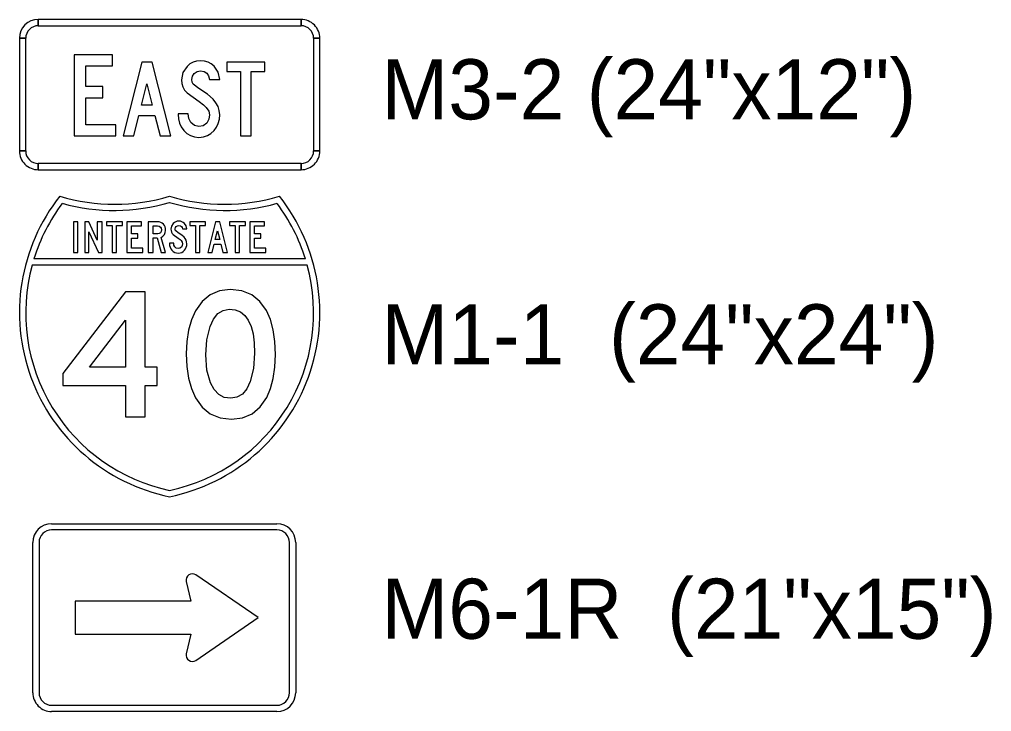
# Model space of a CAD drawing. Extents: x 620864 to 620948.6, y 415499.7 to 415559.1.
# Drawn here: x 620888.77 to 620895.24, y 415510.86 to 415515.47 of the extents above; entities that cross this region are included whole.
import ezdxf

# ---------------------------------------------------------------- set-up
doc = ezdxf.new("R2010")
doc.units = 0
doc.layers.add('SIGNS', color=7, linetype='Continuous')

msp = doc.modelspace()

# ---------------------------------------------------------------- linework, layer by layer
at = {"layer": 'SIGNS'}
for p, q in [((620888.8903, 415515.4272), (620888.8903, 415515.4688)), ((620890.6403, 415515.4688), (620890.6403, 415515.4272)), ((620888.7653, 415515.3438), (620888.807, 415515.3438)), ((620890.7237, 415515.3438), (620890.7653, 415515.3438)), ((620888.807, 415514.5938), (620888.7653, 415514.5938)), ((620890.7653, 415514.5938), (620890.7237, 415514.5938)), ((620888.8903, 415514.4688), (620888.8903, 415514.5105)), ((620890.6403, 415514.5105), (620890.6403, 415514.4688)), ((620889.1535, 415514.1225), (620889.1247, 415514.1225)), ((620889.1247, 415514.1225), (620889.1247, 415513.9182)), ((620889.1535, 415513.9182), (620889.1535, 415514.1225)), ((620889.2277, 415514.1225), (620889.1997, 415514.1225)), ((620889.1997, 415514.1225), (620889.1997, 415513.9182)), ((620889.2838, 415514.0007), (620889.2277, 415514.1225)), ((620889.3151, 415514.1225), (620889.2838, 415514.1225)), ((620889.2838, 415514.1225), (620889.2838, 415514.0007)), ((620889.3151, 415513.9182), (620889.3151, 415514.1225)), ((620889.4506, 415514.1225), (620889.3455, 415514.1225)), ((620889.3455, 415514.1225), (620889.3455, 415514.0969)), ((620889.3455, 415514.0969), (620889.3828, 415514.0969)), ((620889.3828, 415514.0969), (620889.3828, 415513.9182)), ((620889.4125, 415513.9182), (620889.4125, 415514.0969)), ((620889.4125, 415514.0969), (620889.4506, 415514.0969)), ((620889.4506, 415514.0969), (620889.4506, 415514.1225)), ((620889.5782, 415514.1225), (620889.481, 415514.1225)), ((620889.481, 415514.1225), (620889.481, 415513.9182)), ((620889.5108, 415514.0424), (620889.5108, 415514.0945)), ((620889.5108, 415514.0945), (620889.5782, 415514.0945)), ((620889.5782, 415514.0945), (620889.5782, 415514.1225)), ((620889.7774, 415514.0936), (620889.7735, 415514.0737)), ((620889.789, 415514.1108), (620889.7774, 415514.0936)), ((620889.797, 415514.1177), (620889.789, 415514.1108)), ((620889.8059, 415514.1226), (620889.797, 415514.1177)), ((620889.802, 415514.0745), (620889.8038, 415514.0837)), ((620889.8038, 415514.0837), (620889.8093, 415514.0914)), ((620889.8155, 415514.1255), (620889.8059, 415514.1226)), ((620889.8093, 415514.0914), (620889.8172, 415514.0966)), ((620889.8259, 415514.1266), (620889.8155, 415514.1255)), ((620889.8172, 415514.0966), (620889.8267, 415514.0983)), ((620889.8371, 415514.1256), (620889.8259, 415514.1266)), ((620889.8267, 415514.0983), (620889.8368, 415514.0966)), ((620889.8368, 415514.0966), (620889.8442, 415514.0917)), ((620889.8473, 415514.1228), (620889.8371, 415514.1256)), ((620889.8442, 415514.0917), (620889.8482, 415514.0848)), ((620889.8562, 415514.1182), (620889.8473, 415514.1228)), ((620889.8482, 415514.0848), (620889.8512, 415514.0746)), ((620889.8642, 415514.1118), (620889.8562, 415514.1182)), ((620889.875, 415514.0954), (620889.8642, 415514.1118)), ((620889.8796, 415514.0746), (620889.875, 415514.0954)), ((620890.0048, 415514.1225), (620889.8997, 415514.1225)), ((620889.8997, 415514.1225), (620889.8997, 415514.0969)), ((620889.8997, 415514.0969), (620889.937, 415514.0969)), ((620889.937, 415514.0969), (620889.937, 415513.9182)), ((620889.9667, 415513.9182), (620889.9667, 415514.0969)), ((620889.9667, 415514.0969), (620890.0048, 415514.0969)), ((620890.0048, 415514.0969), (620890.0048, 415514.1225)), ((620890.2694, 415514.1225), (620890.1643, 415514.1225)), ((620890.1643, 415514.1225), (620890.1643, 415514.0969)), ((620890.1643, 415514.0969), (620890.2016, 415514.0969)), ((620890.2016, 415514.0969), (620890.2016, 415513.9182)), ((620890.2312, 415513.9182), (620890.2312, 415514.0969)), ((620890.2312, 415514.0969), (620890.2694, 415514.0969)), ((620890.2694, 415514.0969), (620890.2694, 415514.1225)), ((620890.397, 415514.1225), (620890.2997, 415514.1225)), ((620890.2997, 415514.1225), (620890.2997, 415513.9182)), ((620890.3296, 415514.0424), (620890.3296, 415514.0945)), ((620890.3296, 415514.0945), (620890.397, 415514.0945)), ((620890.397, 415514.0945), (620890.397, 415514.1225)), ((620889.2277, 415513.9182), (620889.2277, 415514.0562)), ((620889.2277, 415514.0562), (620889.2922, 415513.9182)), ((620889.5535, 415514.0424), (620889.5108, 415514.0424)), ((620889.5535, 415514.0144), (620889.5535, 415514.0424)), ((620889.7735, 415514.0737), (620889.7745, 415514.0634)), ((620889.7745, 415514.0634), (620889.7774, 415514.0541)), ((620889.7774, 415514.0541), (620889.7823, 415514.0454)), ((620889.7823, 415514.0454), (620889.7892, 415514.0375)), ((620889.7892, 415514.0375), (620889.8224, 415514.0137)), ((620889.8031, 415514.0677), (620889.802, 415514.0745)), ((620889.8065, 415514.0618), (620889.8031, 415514.0677)), ((620889.8222, 415514.05), (620889.8065, 415514.0618)), ((620889.8459, 415514.0337), (620889.8222, 415514.05)), ((620889.8613, 415514.0204), (620889.8459, 415514.0337)), ((620889.8512, 415514.0746), (620889.8796, 415514.0746)), ((620889.8693, 415514.0104), (620889.8613, 415514.0204)), ((620890.3722, 415514.0424), (620890.3296, 415514.0424)), ((620890.3722, 415514.0144), (620890.3722, 415514.0424)), ((620889.5108, 415513.9463), (620889.5108, 415514.0144)), ((620889.5108, 415514.0144), (620889.5535, 415514.0144)), ((620889.7925, 415513.9796), (620889.7643, 415513.9796)), ((620889.7643, 415513.9796), (620889.7643, 415513.9777)), ((620889.7643, 415513.9777), (620889.7652, 415513.9653)), ((620889.7652, 415513.9653), (620889.7681, 415513.9538)), ((620889.7681, 415513.9538), (620889.7731, 415513.9432)), ((620889.7942, 415513.9662), (620889.7925, 415513.9796)), ((620889.7999, 415513.9551), (620889.7942, 415513.9662)), ((620889.8096, 415513.9467), (620889.7999, 415513.9551)), ((620889.8224, 415514.0137), (620889.8347, 415514.0044)), ((620889.8436, 415513.954), (620889.8339, 415513.9465)), ((620889.8347, 415514.0044), (620889.8423, 415513.9974)), ((620889.8423, 415513.9974), (620889.8491, 415513.9872)), ((620889.8494, 415513.9642), (620889.8436, 415513.954)), ((620889.8491, 415513.9872), (620889.8514, 415513.9763)), ((620889.8514, 415513.9763), (620889.8494, 415513.9642)), ((620889.875, 415513.9997), (620889.8693, 415514.0104)), ((620889.8708, 415513.9424), (620889.8757, 415513.9529)), ((620889.8784, 415513.9884), (620889.875, 415513.9997)), ((620889.8757, 415513.9529), (620889.8787, 415513.9642)), ((620889.8796, 415513.9766), (620889.8784, 415513.9884)), ((620889.8787, 415513.9642), (620889.8796, 415513.9766)), ((620890.3296, 415513.9463), (620890.3296, 415514.0144)), ((620890.3296, 415514.0144), (620890.3722, 415514.0144)), ((620889.1247, 415513.9182), (620889.1535, 415513.9182)), ((620889.1997, 415513.9182), (620889.2277, 415513.9182)), ((620889.2922, 415513.9182), (620889.3151, 415513.9182)), ((620889.3828, 415513.9182), (620889.4125, 415513.9182)), ((620889.481, 415513.9182), (620889.586, 415513.9182)), ((620889.586, 415513.9463), (620889.5108, 415513.9463)), ((620889.586, 415513.9182), (620889.586, 415513.9463)), ((620889.7731, 415513.9432), (620889.7801, 415513.9336)), ((620889.7801, 415513.9336), (620889.7889, 415513.925)), ((620889.7889, 415513.925), (620889.799, 415513.919)), ((620889.799, 415513.919), (620889.81, 415513.9154)), ((620889.8222, 415513.9439), (620889.8096, 415513.9467)), ((620889.81, 415513.9154), (620889.8222, 415513.9142)), ((620889.8339, 415513.9465), (620889.8222, 415513.9439)), ((620889.8222, 415513.9142), (620889.8343, 415513.9154)), ((620889.8343, 415513.9154), (620889.8454, 415513.9189)), ((620889.8454, 415513.9189), (620889.8552, 415513.9247)), ((620889.8552, 415513.9247), (620889.864, 415513.933)), ((620889.864, 415513.933), (620889.8708, 415513.9424)), ((620889.937, 415513.9182), (620889.9667, 415513.9182)), ((620890.2016, 415513.9182), (620890.2312, 415513.9182)), ((620890.2997, 415513.9182), (620890.4048, 415513.9182)), ((620890.4048, 415513.9463), (620890.3296, 415513.9463)), ((620890.4048, 415513.9182), (620890.4048, 415513.9463)), ((620890.6692, 415513.8766), (620888.8615, 415513.8766)), ((620888.9793, 415512.1134), (620890.4793, 415512.1134)), ((620890.4793, 415512.1134), (620890.4793, 415512.1134)), ((620890.4793, 415512.0717), (620888.9793, 415512.0717)), ((620888.8543, 415510.9884), (620888.8543, 415511.9884)), ((620888.8959, 415511.9884), (620888.8959, 415510.9884)), ((620890.5626, 415510.9884), (620890.5626, 415511.9884)), ((620890.6043, 415511.9884), (620890.6043, 415510.9884)), ((620890.3543, 415511.4884), (620889.939, 415511.7736)), ((620889.8761, 415511.729), (620889.9063, 415511.5978)), ((620889.9063, 415511.5978), (620889.1355, 415511.5978)), ((620889.1355, 415511.5978), (620889.1355, 415511.379)), ((620889.939, 415511.2032), (620890.3543, 415511.4884)), ((620889.1355, 415511.379), (620889.9063, 415511.379)), ((620889.9063, 415511.379), (620889.8761, 415511.2477)), ((620888.9793, 415510.9051), (620890.4793, 415510.9051)), ((620890.4793, 415510.8634), (620888.9793, 415510.8634)), ((620888.9793, 415510.8634), (620888.9793, 415510.8634))]:
    msp.add_line(p, q, dxfattribs=at)
for points in [[(620890.6403, 415515.4688), (620888.8903, 415515.4688), (620888.8903, 415515.4272), (620890.6403, 415515.4272), (620890.6403, 415515.4688), (620890.6403, 415515.4688)], [(620888.7653, 415515.3438), (620888.7653, 415514.5938), (620888.807, 415514.5938), (620888.807, 415515.3438), (620888.7653, 415515.3438), (620888.7653, 415515.3438)], [(620890.7653, 415514.5938), (620890.7653, 415515.3438), (620890.7237, 415515.3438), (620890.7237, 415514.5938), (620890.7653, 415514.5938), (620890.7653, 415514.5938)], [(620889.4063, 415514.7678), (620889.2077, 415514.7678), (620889.2077, 415514.9476), (620889.3204, 415514.9476), (620889.3204, 415515.0217), (620889.2077, 415515.0217), (620889.2077, 415515.1592), (620889.3857, 415515.1592), (620889.3857, 415515.2332), (620889.1289, 415515.2332), (620889.1289, 415514.6938), (620889.4063, 415514.6938)], [(620889.8217, 415514.8412), (620889.8217, 415514.8367), (620889.8237, 415514.8068), (620889.8308, 415514.7792), (620889.8428, 415514.7538), (620889.8596, 415514.7306), (620889.8808, 415514.7102), (620889.9049, 415514.6958), (620889.9313, 415514.6871), (620889.9606, 415514.6843), (620889.9898, 415514.6869), (620890.0164, 415514.6955), (620890.0399, 415514.7095), (620890.061, 415514.7292), (620890.0773, 415514.7519), (620890.0891, 415514.777), (620890.0961, 415514.8042), (620890.0985, 415514.834), (620890.0956, 415514.8624), (620890.0874, 415514.8894), (620890.0736, 415514.915), (620890.0545, 415514.9391), (620890.0175, 415514.971), (620889.9606, 415515.0101), (620889.9229, 415515.0383), (620889.9148, 415515.0526), (620889.9121, 415515.069), (620889.9165, 415515.0909), (620889.9296, 415515.1094), (620889.9487, 415515.1218), (620889.9714, 415515.126), (620889.9957, 415515.122), (620890.0135, 415515.1103), (620890.0231, 415515.0936), (620890.0303, 415515.0691), (620890.0985, 415515.0691), (620890.0874, 415515.1191), (620890.0614, 415515.1585), (620890.0424, 415515.1738), (620890.0209, 415515.1849), (620889.9963, 415515.1916), (620889.9695, 415515.1938), (620889.9445, 415515.1914), (620889.9215, 415515.1843), (620889.9002, 415515.1725), (620889.881, 415515.1559), (620889.853, 415515.1148), (620889.8439, 415515.067), (620889.8461, 415515.0423), (620889.8532, 415515.0198), (620889.8649, 415514.9989), (620889.8814, 415514.98), (620889.9611, 415514.9231), (620889.9907, 415514.9006), (620890.009, 415514.8838), (620890.0252, 415514.8594), (620890.0308, 415514.8332), (620890.0259, 415514.8042), (620890.012, 415514.7796), (620889.9888, 415514.7616), (620889.9606, 415514.7555), (620889.9304, 415514.7622), (620889.9071, 415514.7823), (620889.8934, 415514.8091), (620889.8894, 415514.8412)], [(620890.2362, 415514.6938), (620890.3074, 415514.6938), (620890.3074, 415515.1226), (620890.3989, 415515.1226), (620890.3989, 415515.1842), (620890.1467, 415515.1842), (620890.1467, 415515.1226), (620890.2362, 415515.1226)], [(620888.8903, 415514.4688), (620890.6403, 415514.4688), (620890.6403, 415514.5105), (620888.8903, 415514.5105), (620888.8903, 415514.4688), (620888.8903, 415514.4688)]]:
    msp.add_lwpolyline(points, close=True, dxfattribs=at)
for points in [[(620889.4567, 415514.6938), (620889.5278, 415514.6938), (620889.561, 415514.8288), (620889.6668, 415514.8288), (620889.7015, 415514.6938), (620889.7732, 415514.6938), (620889.6495, 415515.1842), (620889.5803, 415515.1842), (620889.4567, 415514.6938)], [(620889.5783, 415514.8986), (620889.6129, 415515.041), (620889.6495, 415514.8986), (620889.5783, 415514.8986)], [(620889.0348, 415514.2932), (620889.0348, 415514.2932)], [(620890.4959, 415514.2932), (620890.4959, 415514.2932)], [(620889.0504, 415514.2452), (620889.0504, 415514.2452)], [(620889.7653, 415514.2516), (620889.7653, 415514.2516)], [(620890.4803, 415514.2452), (620890.4803, 415514.2452)], [(620889.6547, 415513.9182), (620889.6547, 415514.0155), (620889.682, 415514.0155), (620889.7087, 415513.9182), (620889.738, 415513.9182), (620889.7083, 415514.0189), (620889.721, 415514.0261), (620889.7306, 415514.0373), (620889.7361, 415514.0504), (620889.738, 415514.0653), (620889.7371, 415514.0776), (620889.7345, 415514.0886), (620889.7301, 415514.0983), (620889.7241, 415514.1066), (620889.7162, 415514.1135), (620889.7068, 415514.1185), (620889.696, 415514.1216), (620889.6838, 415514.1225), (620889.6226, 415514.1225), (620889.6226, 415513.9182), (620889.6547, 415513.9182)], [(620889.6547, 415514.0424), (620889.6547, 415514.0945), (620889.6846, 415514.0945), (620889.6952, 415514.0927), (620889.7035, 415514.0874), (620889.7089, 415514.0791), (620889.7107, 415514.0683), (620889.7091, 415514.0569), (620889.7044, 415514.0489), (620889.6966, 415514.044), (620889.6856, 415514.0424), (620889.6547, 415514.0424)], [(620890.0481, 415513.9182), (620890.0619, 415513.9745), (620890.106, 415513.9745), (620890.1205, 415513.9182), (620890.1503, 415513.9182), (620890.0988, 415514.1225), (620890.07, 415514.1225), (620890.0185, 415513.9182), (620890.0481, 415513.9182)], [(620890.0691, 415514.0035), (620890.0836, 415514.0629), (620890.0988, 415514.0035), (620890.0691, 415514.0035)], [(620888.8493, 415513.8349), (620889.3918, 415513.8349), (620889.9188, 415513.8349), (620890.6814, 415513.8349)], [(620889.4703, 415512.8255), (620889.6026, 415512.8255), (620889.6026, 415513.034), (620889.6822, 415513.034), (620889.6822, 415513.1546), (620889.6026, 415513.1546), (620889.6026, 415513.6558), (620889.4703, 415513.6558), (620889.0541, 415513.1127), (620889.0541, 415513.034), (620889.4703, 415513.034), (620889.4703, 415512.8255)], [(620890.1692, 415513.6721), (620890.0967, 415513.6631), (620890.0341, 415513.6365), (620889.9809, 415513.5919), (620889.9374, 415513.5299), (620889.9102, 415513.469), (620889.8909, 415513.4013), (620889.8791, 415513.3263), (620889.8754, 415513.2445), (620889.8791, 415513.159), (620889.8909, 415513.0816), (620889.9102, 415513.0124), (620889.9374, 415512.9514), (620889.9814, 415512.889), (620890.0361, 415512.8445), (620890.101, 415512.8179), (620890.1768, 415512.8092), (620890.2509, 415512.8181), (620890.3147, 415512.845), (620890.3682, 415512.8901), (620890.4114, 415512.9531), (620890.4368, 415513.0124), (620890.4551, 415513.0801), (620890.4661, 415513.1557), (620890.4699, 415513.2393), (620890.4661, 415513.3258), (620890.4549, 415513.4034), (620890.4363, 415513.4718), (620890.4104, 415513.5314), (620890.3666, 415513.5928), (620890.312, 415513.6367), (620890.246, 415513.6631), (620890.1692, 415513.6721)], [(620890.3313, 415513.2483), (620890.3238, 415513.1452), (620890.3022, 415513.0593), (620890.2789, 415513.0104), (620890.2493, 415512.9755), (620890.2135, 415512.9547), (620890.1717, 415512.9478), (620890.1285, 415512.9541), (620890.0918, 415512.9738), (620890.0613, 415513.006), (620890.0369, 415513.0516), (620890.0133, 415513.1358), (620890.0056, 415513.2365), (620890.013, 415513.3362), (620890.0354, 415513.425), (620890.0582, 415513.4755), (620890.0871, 415513.5115), (620890.1214, 415513.5332), (620890.1618, 415513.5406), (620890.2013, 415513.536), (620890.2359, 415513.5223), (620890.2648, 415513.4993), (620890.2888, 415513.4673), (620890.3071, 415513.426), (620890.3205, 415513.3759), (620890.3285, 415513.3164), (620890.3313, 415513.2483)], [(620889.4703, 415513.1546), (620889.2307, 415513.1546), (620889.4703, 415513.4685), (620889.4703, 415513.1546)], [(620889.7653, 415512.3349), (620889.7653, 415512.3349)], [(620889.7653, 415512.2932), (620889.7653, 415512.2932)], [(620888.9793, 415512.1134), (620888.9793, 415512.1134)], [(620888.8543, 415511.9884), (620888.8543, 415511.9884)], [(620890.6043, 415510.9884), (620890.6043, 415510.9884)], [(620890.4793, 415510.8634), (620890.4793, 415510.8634)]]:
    msp.add_lwpolyline(points, dxfattribs=at)
for centre, radius, start, end in [((620888.8903, 415515.3438), 0.125, 90.00021, 179.99985), ((620890.6403, 415515.3438), 0.125, 360, 90.00021), ((620888.8903, 415515.3438), 0.0833, 90.00021, 179.99985), ((620890.6403, 415515.3438), 0.0833, 360, 90.00021), ((620888.8903, 415514.5938), 0.125, 179.99985, 270.00006), ((620888.8903, 415514.5938), 0.0833, 179.99985, 270.00006), ((620890.6403, 415514.5938), 0.125, 270.00006, 0.00027), ((620890.6403, 415514.5938), 0.0833, 270.00006, 0.00027), ((620890.0153, 415513.518), 1.25, 141.66897, 258.46298), ((620889.4001, 415515.4886), 1.25, 253.009, 286.99091), ((620889.5153, 415513.518), 1.25, 281.53714, 38.33115), ((620890.1306, 415515.4886), 1.25, 253.00909, 286.99112), ((620890.0151, 415513.5171), 1.2083, 142.99594, 162.69525), ((620889.3969, 415515.4896), 1.2917, 254.4391, 286.57458), ((620890.1338, 415515.4896), 1.2917, 253.42554, 285.56102), ((620889.5156, 415513.5171), 1.2083, 17.30466, 37.00414), ((620890.0151, 415513.5171), 1.2083, 164.75344, 258.07036), ((620889.5156, 415513.5171), 1.2083, 281.92964, 15.24668), ((620889.5156, 415513.5171), 1.2083, 281.92961, 281.92964), ((620890.0151, 415513.5171), 1.2083, 258.07036, 258.0705), ((620888.9793, 415511.9884), 0.125, 90.00021, 179.99985), ((620890.4793, 415511.9884), 0.125, 360, 90), ((620888.9793, 415511.9884), 0.0833, 90.00021, 179.99985), ((620890.4793, 415511.9884), 0.0833, 360, 90.00021), ((620889.9168, 415511.7384), 0.0417, 57.72435, 192.95041), ((620889.9168, 415511.2384), 0.0417, 167.04986, 302.27592), ((620888.9793, 415510.9884), 0.125, 179.99985, 270), ((620888.9793, 415510.9884), 0.0833, 179.99985, 270.00006), ((620890.4793, 415510.9884), 0.125, 270.00006, 360), ((620890.4793, 415510.9884), 0.0833, 270.00006, 0.00027)]:
    msp.add_arc(centre, radius, start, end, dxfattribs=at)

# ---------------------------------------------------------------- texts
for s, p in [('M3-2 (24"x12")', (620891.1748, 415514.804)), ('M1-1  (24"x24")', (620891.1748, 415513.1732)), ('M6-1R  (21"x15")', (620891.1748, 415511.3476))]:
    msp.add_text(s, height=0.4, rotation=0, dxfattribs=at).set_placement(p)

doc.saveas('drawing.dxf')
